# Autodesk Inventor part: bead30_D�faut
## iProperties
Created: 2011-01
Part Number: bead30_D�faut
Document SubType Name: Modeling
Designer: eric
Density: 1 g/cm^3
Mass: 0.0717811 g
Surface Area: 2.42706 cm^2
Volume: 0.0717811 cm^3
Author: eric
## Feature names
1. Base1
